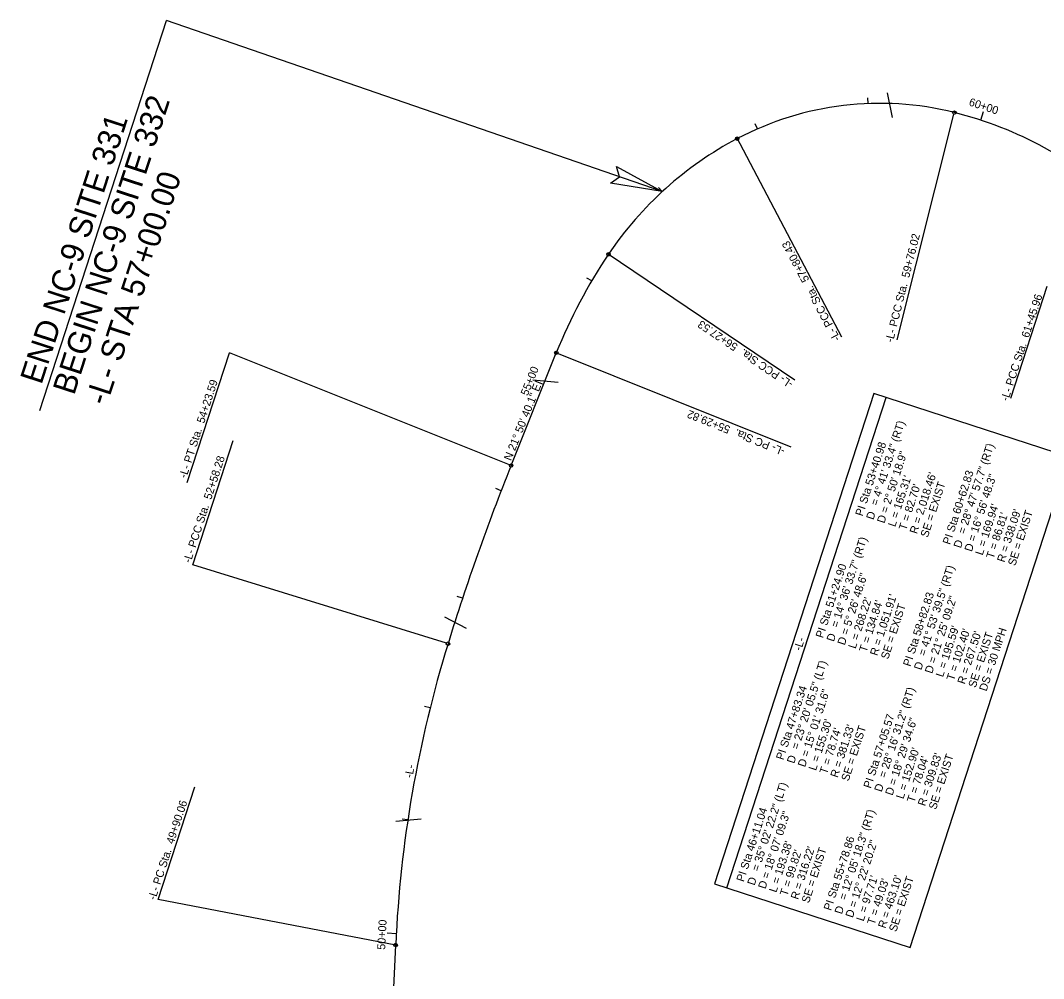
# Model space of a CAD drawing. Extents: x 1019959 to 1023888, y 635993 to 644996.
# Drawn here: x 1021729 to 1022623, y 639427 to 640265 of the extents above; entities that cross this region are included whole.
import ezdxf

# ---------------------------------------------------------------- set-up
doc = ezdxf.new("R2010")
doc.units = 0
for name, color, linetype in [('Cogo Default Point CELL', 7, 'Continuous'), ('COGO Default Point Elevation', 7, 'Continuous'), ('COGO Default Point Number', 7, 'Continuous'), ('Exist Other Culture Well CELL', 7, 'Continuous'), ('Exist Roads EOT', 7, 'Continuous'), ('Exist Structure Minor Pipes CMP 18 Inch Cogo Comment', 7, 'Continuous'), ('Exist Structure Minor Pipes CMP 18 Inch Cogo Number', 7, 'Continuous'), ('Exist Structure Minor Pipes CMP 24 Inch Cogo Number', 7, 'Continuous'), ('Exist Utilities Power Pole CELL', 7, 'Continuous'), ('Exist Utilities Power Pole Cogo Elevation', 7, 'Continuous'), ('Exist Utilities Power Pole Cogo Number', 7, 'Continuous')]:
    doc.layers.add(name, color=color, linetype=linetype)

msp = doc.modelspace()

# ---------------------------------------------------------------- linework, layer by layer
at = {"layer": 'COGO Default Point Elevation'}
for p, q in [((1022470, 640192.41), (1022469.81, 640197.41)), ((1022373.09, 640170.23), (1022371.09, 640174.81)), ((1022289.94, 640115.48), (1022286.56, 640119.16)), ((1022228.18, 640037.33), (1022223.87, 640039.87)), ((1022149.06, 639853.86), (1022144.4, 639855.67)), ((1022115.27, 639759.75), (1022110.52, 639761.33)), ((1022086.92, 639663.88), (1022082.06, 639665.09)), ((1022067.41, 639565.84), (1022062.46, 639566.59))]:
    msp.add_line(p, q, dxfattribs=at)
at = {"layer": 'COGO Default Point Number'}
for p, q in [((1022568.39, 640177.88), (1022570.88, 640185.48)), ((1022186.14, 639946.73), (1022178.72, 639949.71)), ((1022057.29, 639466.39), (1022049.3, 639466.83))]:
    msp.add_line(p, q, dxfattribs=at)
at = {"layer": 'Exist Other Culture Well CELL'}
for p in [(1021745.45, 639924.03), (1022289.94, 640115.48)]:
    msp.add_line(p, (1021856.35, 640265.13), dxfattribs=at)
at = {"layer": 'Exist Roads EOT'}
for p, q in [((1022495.4, 639985.68), (1022544.99, 640183.09)), ((1022354.76, 640163.07), (1022446.78, 639988.49)), ((1022241.61, 640061.45), (1022405.9, 639950.91)), ((1022594.76, 639934.75), (1022626.6, 640032.7)), ((1021874.5, 639860.99), (1021911.42, 639974.54)), ((1022156.32, 639876.37), (1021911.42, 639974.54)), ((1022195.85, 639974.97), (1022402.43, 639892.16)), ((1021879.37, 639788.9), (1021914.74, 639897.71)), ((1022101.12, 639720.46), (1021879.37, 639788.9)), ((1021849.1, 639496.42), (1021881.11, 639594.88)), ((1022056.8, 639456.47), (1021849.1, 639496.42))]:
    msp.add_line(p, q, dxfattribs=at)
for centre in [(1022545.36, 640184.54), (1022355.46, 640161.75), (1022242.86, 640060.61), (1022197.24, 639974.41), (1022157.71, 639875.81), (1022102.55, 639720.02), (1022056.8, 639456.47)]:
    msp.add_circle(centre, 1.5, dxfattribs=at)
at = {"layer": 'Exist Structure Minor Pipes CMP 18 Inch Cogo Comment'}
msp.add_lwpolyline([(1022249.94, 640137.49), (1022289.94, 640115.48), (1022244.56, 640122.68), (1022252.61, 640128.37)], close=True, dxfattribs=at)
at = {"layer": 'Exist Structure Minor Pipes CMP 18 Inch Cogo Number'}
for p, q in [((1022157.71, 639875.81), (1022197.24, 639974.41)), ((1022051.03, 639326.43), (1022056.8, 639456.47))]:
    msp.add_line(p, q, dxfattribs=at)
for centre, radius, start, end in [((1022480.18, 639925.11), 267.5, 75.89747, 117.79178), ((1022462.98, 639856.64), 338.09, 47.09809, 75.89747), ((1022499.92, 639887.66), 309.83, 117.79178, 146.06711), ((1022627.09, 639802.1), 463.1, 146.06711, 158.15553), ((1024031.24, 639124.77), 2018.46, 158.15553, 162.84813), ((1023107.68, 639409.81), 1051.91, 162.84813, 177.45749)]:
    msp.add_arc(centre, radius, start, end, dxfattribs=at)
at = {"layer": 'Exist Structure Minor Pipes CMP 24 Inch Cogo Number'}
for p, q in [((1022491.16, 640180.24), (1022486.78, 640201.79)), ((1022176.64, 639950.83), (1022199, 639948.75)), ((1022099.59, 639743.5), (1022118.29, 639733.6)), ((1022078.97, 639566.68), (1022056.97, 639564.38))]:
    msp.add_line(p, q, dxfattribs=at)
at = {"layer": 'Exist Utilities Power Pole CELL'}
for p, q in [((1022157.71, 639875.81), (1022197.24, 639974.41)), ((1022051.03, 639326.43), (1022056.8, 639456.47))]:
    msp.add_line(p, q, dxfattribs=at)
for centre, radius, start, end in [((1022480.18, 639925.11), 267.5, 75.89747, 117.79178), ((1022462.98, 639856.64), 338.09, 47.0981, 75.89747), ((1022499.92, 639887.66), 309.83, 117.79178, 146.06711), ((1022627.09, 639802.1), 463.1, 146.06711, 158.15553), ((1024031.24, 639124.77), 2018.46, 158.15553, 162.84813), ((1023107.68, 639409.81), 1051.91, 162.84813, 177.45749)]:
    msp.add_arc(centre, radius, start, end, dxfattribs=at)
at = {"layer": 'Exist Utilities Power Pole Cogo Elevation'}
msp.add_line((1022346.33, 639506.51), (1022485.74, 639935.3), dxfattribs=at)
msp.add_lwpolyline([(1022506.76, 639454.35), (1022646.17, 639883.14), (1022474.92, 639938.83), (1022335.5, 639510.03)], close=True, dxfattribs=at)

# ---------------------------------------------------------------- texts
at = {"layer": 'Cogo Default Point CELL'}
for s, rotation, p in [('60+00', 341.83375, (1022557.48, 640190.93)), ('55+00', 68.15553, (1022172.29, 639936.37)), ('50+00', 86.91619, (1022047.52, 639452.24))]:
    msp.add_text(s, height=7, rotation=rotation, dxfattribs=at).set_placement(p)
at = {"layer": 'Exist Other Culture Well CELL'}
for s, p in [('BEGIN NC-9 SITE 332', (1021775.52, 639936.7)), ('END NC-9 SITE 331', (1021746.99, 639945.97)), ('-L- STA 57+00.00', (1021804.05, 639927.42))]:
    msp.add_text(s, height=20, rotation=71.9892, dxfattribs=at).set_placement(p)
at = {"layer": 'Exist Roads EOT'}
for s, rotation, p in [('-L- PCC Sta.  59+76.02', 75.89747, (1022491.58, 639983.07)), ('-L- PCC Sta.  57+80.43', 117.79178, (1022445.86, 639986.76)), ('-L- PCC Sta.  61+45.96', 71.99034, (1022592.32, 639931.64)), ('-L- PCC Sta.  56+27.53', 146.06711, (1022404.96, 639948.8)), ('-L- PT Sta.  54+23.59', 71.99034, (1021873.64, 639864.27)), ('-L- PC Sta.  55+29.82', 158.15553, (1022397.78, 639890.79)), ('-L- PCC Sta.  52+58.28', 71.99034, (1021877.4, 639790.17)), ('-L- PC Sta.  49+90.06', 71.99034, (1021846.64, 639495.33))]:
    msp.add_text(s, height=7, rotation=rotation, dxfattribs=at).set_placement(p)
at = {"layer": 'Exist Utilities Power Pole Cogo Elevation'}
for s, rotation, p in [('= 4%%d 41\' 33.4" (RT)', 71.9892, (1022478.29, 639840.26)), ('PI Sta 53+40.98', 71.9892, (1022465.09, 639831.04)), ('= 28%%d 47\' 57.7" (RT)', 71.9892, (1022554.74, 639815.4)), ('D = 2%%d 50\' 18.9"', 71.9892, (1022484.11, 639824.85)), ("L = 165.31'", 71.9892, (1022493.62, 639821.76)), ("R = 2,018.46'", 71.9892, (1022512.64, 639815.58)), ('PI Sta 60+62.83', 71.9892, (1022541.53, 639806.18)), ('D = 16%%d 56\' 48.3"', 71.9892, (1022560.55, 639800)), ("T = 82.70'", 71.9892, (1022503.13, 639818.67)), ('SE = EXIST', 71.9892, (1022522.15, 639812.48)), ("L = 169.94'", 71.9892, (1022570.06, 639796.9)), ("R = 338.09'", 71.9892, (1022589.08, 639790.72)), ('SE = EXIST', 71.9892, (1022598.59, 639787.63)), ('D', 71.9892, (1022474.6, 639827.94)), ("T = 86.81'", 71.9892, (1022579.57, 639793.81)), ('= 14%%d 36\' 33.7" (RT)', 71.9892, (1022443.63, 639733.65)), ('D', 71.9892, (1022551.04, 639803.09)), ('PI Sta 51+24.90', 71.9892, (1022430.43, 639724.43)), ('= 41%%d 53\' 39.5" (RT)', 71.9892, (1022520.08, 639708.8)), ('D = 5%%d 26\' 48.6"', 71.9892, (1022449.45, 639718.25)), ("L = 268.22'", 71.9892, (1022458.96, 639715.16)), ("T = 134.84'", 71.9892, (1022468.47, 639712.06)), ("R = 1,051.91'", 71.9892, (1022477.98, 639708.97)), ('PI Sta 58+82.83', 71.9892, (1022506.88, 639699.58)), ('D = 21%%d 25\' 09.2"', 71.9892, (1022525.9, 639693.39)), ('SE = EXIST', 71.9892, (1022487.49, 639705.88)), ("L = 195.59'", 71.9892, (1022535.41, 639690.3)), ("T = 102.40'", 71.9892, (1022544.92, 639687.21)), ("R = 267.50'", 71.9892, (1022554.43, 639684.12)), ('SE = EXIST', 71.9892, (1022563.94, 639681.03)), ('DS = 30 MPH', 71.9892, (1022573.45, 639677.93)), ('-L-', 71.9892, (1022411.28, 639713.37)), ('D', 71.9892, (1022439.94, 639721.34)), ('= 23%%d 20\' 05.5" (LT)', 71.9892, (1022408.97, 639627.05)), ('D', 71.9892, (1022516.39, 639696.49)), ('PI Sta 47+83.34', 71.9892, (1022395.77, 639617.83)), ('D = 15%%d 01\' 31.6"', 71.9892, (1022414.79, 639611.64)), ('= 28%%d 16\' 31.2" (RT)', 71.9892, (1022485.42, 639602.19)), ('PI Sta 57+05.57', 71.9892, (1022472.22, 639592.97)), ("L = 155.30'", 71.9892, (1022424.3, 639608.55)), ("R = 381.33'", 71.9892, (1022443.32, 639602.37)), ('SE = EXIST', 71.9892, (1022452.83, 639599.28)), ('D = 18%%d 29\' 34.6"', 71.9892, (1022491.24, 639586.79)), ("T = 78.74'", 71.9892, (1022433.81, 639605.46)), ('D', 71.9892, (1022405.28, 639614.74)), ("L = 152.90'", 71.9892, (1022500.75, 639583.7)), ("R = 309.83'", 71.9892, (1022519.77, 639577.51)), ('SE = EXIST', 71.9892, (1022529.28, 639574.42)), ("T = 78.04'", 71.9892, (1022510.26, 639580.61)), ('= 35%%d 02\' 22.2" (LT)', 71.9892, (1022374.31, 639520.45)), ('D', 71.9892, (1022481.73, 639589.88)), ('PI Sta 46+11.04', 71.9892, (1022361.11, 639511.23)), ('D = 18%%d 07\' 09.3"', 71.9892, (1022380.13, 639505.04)), ('= 12%%d 05\' 18.3" (RT)', 71.99034, (1022450.66, 639495.27)), ('PI Sta 55+78.86', 71.99034, (1022437.46, 639486.05)), ("L = 193.38'", 71.9892, (1022389.64, 639501.95)), ("R = 316.22'", 71.9892, (1022408.66, 639495.77)), ('SE = EXIST', 71.9892, (1022418.17, 639492.67)), ('D = 12%%d 22\' 20.2"', 71.99034, (1022456.48, 639479.86)), ("T = 99.82'", 71.9892, (1022399.15, 639498.86)), ('D', 71.9892, (1022370.62, 639508.13)), ("L = 97.71'", 71.99034, (1022465.99, 639476.77)), ("T = 49.03'", 71.99034, (1022475.5, 639473.68)), ("R = 463.10'", 71.99034, (1022485.01, 639470.59)), ('SE = EXIST', 71.9892, (1022494.52, 639467.5)), ('D', 71.99034, (1022446.97, 639482.96))]:
    msp.add_text(s, height=7, rotation=rotation, dxfattribs=at).set_placement(p)
at = {"layer": 'Exist Utilities Power Pole Cogo Number'}
for s, rotation, p in [('N 21%%d 50\' 40.1" E', 68.15553, (1022157.61, 639879.53)), ('-L-', 80.15281, (1022071.44, 639602.28))]:
    msp.add_text(s, height=7, rotation=rotation, dxfattribs=at).set_placement(p)

doc.saveas('drawing.dxf')
